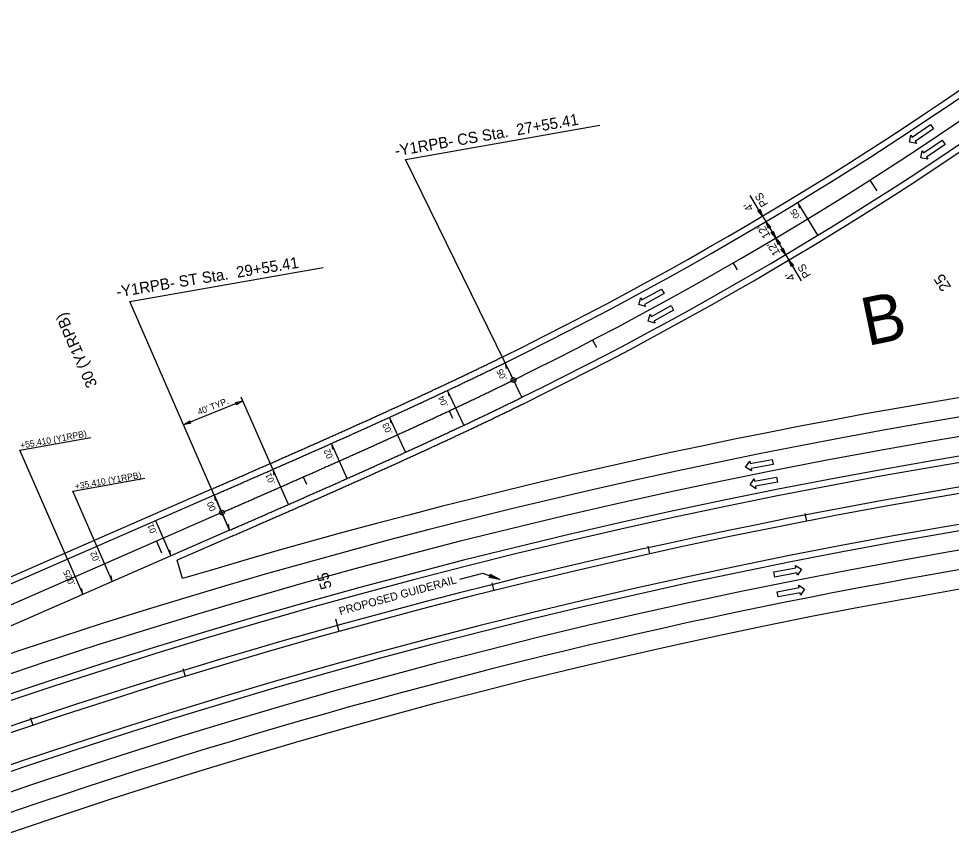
# Model space of a CAD drawing. Extents: x 2389099 to 2405615, y 552200 to 573532.
# Drawn here: x 2393606 to 2394188, y 553993 to 554498 of the extents above; entities that cross this region are included whole.
import ezdxf

# ---------------------------------------------------------------- set-up
doc = ezdxf.new("R2010")
doc.units = 0
for name, color, linetype in [('Old_Level_11', 7, 'Continuous'), ('Prop Cable Guiderail Double Face', 7, 'Continuous'), ('Prop Dimension', 7, 'Continuous'), ('Prop Dimension Text', 7, 'Continuous'), ('Prop DSN Text', 7, 'Continuous'), ('Prop EOT', 7, 'Continuous'), ('Prop Horizontal Alignment', 7, 'Continuous'), ('Prop Horizontal Alignment Curve and Spiral Data', 7, 'Continuous'), ('Prop Horizontal Alignment Tick Large', 7, 'Continuous'), ('Prop Horizontal Alignment Tick Small', 7, 'Continuous'), ('Prop Lane Arrow Through CELL', 7, 'Continuous'), ('Prop Lane Lines', 7, 'Continuous'), ('Prop Super Arrow 1 Lane CELL', 7, 'Continuous'), ('Prop Superelevation Label', 7, 'Continuous')]:
    doc.layers.add(name, color=color, linetype=linetype)

# ---------------------------------------------------------------- blocks, each defined once
blk = doc.blocks.new('TERM')
at = {"layer": 'Old_Level_11'}
blk.add_lwpolyline([(-0.01375, 0.00225), (0, 0), (-0.01375, -0.0025), (-0.012, 0)], close=True, dxfattribs=at)

msp = doc.modelspace()

# ---------------------------------------------------------------- linework, layer by layer
at = {"layer": 'Prop Cable Guiderail Double Face'}
msp.add_arc((2394828.31, 550434.92), 3824, 87.04844, 123.9393, dxfattribs=at)
at = {"layer": 'Prop Dimension'}
for p, q in [((2394070.15, 554374.95), (2394062.49, 554387.84)), ((2394070.15, 554374.95), (2394072.2, 554371.51)), ((2394072.2, 554371.51), (2394078.33, 554361.2)), ((2394078.33, 554361.2), (2394084.47, 554350.88)), ((2394084.47, 554350.88), (2394086.51, 554347.45)), ((2394086.51, 554347.45), (2394094.18, 554334.55)), ((2393745.54, 554259.59), (2393708.53, 554244.62)), ((2393764.32, 554216.83), (2393744.51, 554261.92)), ((2393606.31, 554228.81), (2393650.67, 554236.64)), ((2393636.07, 554160.75), (2393606.31, 554228.81)), ((2393639.3, 554203.29), (2393684.31, 554211.22)), ((2393654.39, 554168.76), (2393639.3, 554203.29))]:
    msp.add_line(p, q, dxfattribs=at)
for points in [[(2394068.52, 554379.21), (2394070.15, 554374.95), (2394067.15, 554378.43), (2394068.13, 554378.34)], [(2394073.83, 554367.25), (2394072.2, 554371.51), (2394075.2, 554368.03), (2394074.22, 554368.12)], [(2394076.7, 554365.46), (2394078.33, 554361.2), (2394075.33, 554364.68), (2394076.31, 554364.59)], [(2394079.97, 554356.93), (2394078.33, 554361.2), (2394081.33, 554357.72), (2394080.35, 554357.8)], [(2394082.83, 554355.15), (2394084.47, 554350.88), (2394081.47, 554354.36), (2394082.45, 554354.28)], [(2394088.15, 554343.18), (2394086.51, 554347.45), (2394089.51, 554343.97), (2394088.53, 554344.05)], [(2393741.07, 554258.62), (2393745.54, 554259.59), (2393741.64, 554257.15), (2393741.87, 554258.11)], [(2393712.99, 554245.59), (2393708.53, 554244.62), (2393712.43, 554247.06), (2393712.19, 554246.11)]]:
    msp.add_lwpolyline(points, close=True, dxfattribs=at)
at = {"layer": 'Prop DSN Text'}
for p, q in [((2393881.08, 554148.27), (2393895.46, 554151.99)), ((2393895.46, 554151.99), (2393906.12, 554148.02))]:
    msp.add_line(p, q, dxfattribs=at)
at = {"layer": 'Prop EOT'}
for p, q in [((2393726.04, 554204.45), (2393359.53, 554044.22)), ((2393727.64, 554200.78), (2393361.13, 554040.55)), ((2393737.25, 554178.79), (2393527.93, 554087.28)), ((2393738.86, 554175.13), (2393704.44, 554160.08)), ((2393707.9, 554148.58), (2393704.44, 554160.08))]:
    msp.add_line(p, q, dxfattribs=at)
for centre, radius, start, end in [((2392902.55, 556337.94), 2284, 296.10428, 342.30241), ((2392902.55, 556337.94), 2288, 296.10428, 342.30241), ((2392902.55, 556337.94), 2312, 296.10428, 342.30241), ((2392902.55, 556337.94), 2316, 296.10428, 342.30241), ((2394828.31, 550434.92), 3879, 67.475, 106.78848), ((2394828.31, 550434.92), 3867, 59.69891, 109.59769), ((2394828.31, 550434.92), 3843, 59.69891, 123.9393), ((2394828.31, 550434.92), 3839, 59.69891, 123.9393), ((2394828.31, 550434.92), 3801, 59.69891, 123.9393), ((2394828.31, 550434.92), 3797, 59.69891, 123.9393), ((2394828.31, 550434.92), 3773, 89.80344, 120.03622), ((2394828.31, 550434.92), 3761, 90.54697, 120.03622)]:
    msp.add_arc(centre, radius, start, end, dxfattribs=at)
for points in [[(2393726.09, 554204.46), (2393728.57, 554205.55), (2393731.05, 554206.63), (2393733.52, 554207.71), (2393736, 554208.79), (2393738.47, 554209.88), (2393740.95, 554210.96), (2393743.42, 554212.04), (2393745.9, 554213.12), (2393748.37, 554214.21), (2393750.84, 554215.29), (2393753.32, 554216.37), (2393755.79, 554217.46), (2393758.26, 554218.54), (2393760.73, 554219.63), (2393763.2, 554220.71), (2393765.67, 554221.8), (2393768.14, 554222.88), (2393770.61, 554223.97), (2393773.08, 554225.06), (2393775.55, 554226.15), (2393778.02, 554227.24), (2393780.49, 554228.33), (2393782.95, 554229.42), (2393785.42, 554230.51), (2393787.89, 554231.6), (2393790.35, 554232.69), (2393792.81, 554233.78), (2393795.28, 554234.88), (2393797.74, 554235.98), (2393800.2, 554237.07), (2393802.66, 554238.17), (2393805.13, 554239.27), (2393807.58, 554240.37), (2393810.04, 554241.47), (2393812.5, 554242.57), (2393814.96, 554243.68), (2393817.42, 554244.78), (2393819.87, 554245.89), (2393822.33, 554246.99), (2393824.78, 554248.1), (2393827.23, 554249.21), (2393829.68, 554250.33), (2393832.13, 554251.44), (2393834.58, 554252.55), (2393837.03, 554253.67), (2393839.48, 554254.79), (2393841.93, 554255.91), (2393844.37, 554257.03), (2393846.82, 554258.15), (2393849.26, 554259.28), (2393851.7, 554260.41), (2393854.14, 554261.54), (2393856.58, 554262.67), (2393859.02, 554263.8), (2393861.46, 554264.93), (2393863.9, 554266.07), (2393866.33, 554267.21), (2393868.77, 554268.35), (2393871.2, 554269.49), (2393873.63, 554270.64), (2393876.06, 554271.79), (2393878.49, 554272.94), (2393880.92, 554274.09), (2393883.34, 554275.24), (2393885.77, 554276.4), (2393888.19, 554277.56), (2393890.61, 554278.72), (2393893.03, 554279.89), (2393895.45, 554281.05), (2393897.87, 554282.22), (2393900.28, 554283.39), (2393902.7, 554284.57), (2393905.11, 554285.74), (2393907.53, 554286.93)], [(2393727.7, 554200.8), (2393730.17, 554201.88), (2393732.65, 554202.96), (2393735.12, 554204.05), (2393737.6, 554205.13), (2393740.08, 554206.21), (2393742.55, 554207.29), (2393745.03, 554208.38), (2393747.5, 554209.46), (2393749.97, 554210.54), (2393752.45, 554211.63), (2393754.92, 554212.71), (2393757.4, 554213.8), (2393759.87, 554214.88), (2393762.34, 554215.96), (2393764.81, 554217.05), (2393767.28, 554218.14), (2393769.75, 554219.22), (2393772.23, 554220.31), (2393774.7, 554221.4), (2393777.17, 554222.49), (2393779.64, 554223.58), (2393782.1, 554224.67), (2393784.57, 554225.76), (2393787.04, 554226.85), (2393789.51, 554227.94), (2393791.97, 554229.03), (2393794.44, 554230.13), (2393796.9, 554231.22), (2393799.37, 554232.32), (2393801.83, 554233.42), (2393804.29, 554234.52), (2393806.76, 554235.62), (2393809.22, 554236.72), (2393811.68, 554237.82), (2393814.14, 554238.92), (2393816.6, 554240.03), (2393819.06, 554241.13), (2393821.52, 554242.24), (2393823.97, 554243.35), (2393826.43, 554244.46), (2393828.88, 554245.57), (2393831.34, 554246.68), (2393833.79, 554247.8), (2393836.24, 554248.91), (2393838.69, 554250.03), (2393841.14, 554251.15), (2393843.59, 554252.27), (2393846.04, 554253.4), (2393848.49, 554254.52), (2393850.94, 554255.65), (2393853.38, 554256.78), (2393855.83, 554257.91), (2393858.27, 554259.04), (2393860.71, 554260.17), (2393863.15, 554261.31), (2393865.59, 554262.45), (2393868.03, 554263.59), (2393870.47, 554264.73), (2393872.9, 554265.88), (2393875.34, 554267.02), (2393877.77, 554268.17), (2393880.2, 554269.32), (2393882.63, 554270.48), (2393885.06, 554271.63), (2393887.49, 554272.79), (2393889.92, 554273.95), (2393892.34, 554275.12), (2393894.77, 554276.28), (2393897.19, 554277.45), (2393899.61, 554278.62), (2393902.03, 554279.79), (2393904.45, 554280.97), (2393906.87, 554282.15), (2393909.29, 554283.33)], [(2393737.31, 554178.81), (2393739.79, 554179.89), (2393742.26, 554180.97), (2393744.74, 554182.06), (2393747.22, 554183.14), (2393749.69, 554184.22), (2393752.17, 554185.31), (2393754.65, 554186.39), (2393757.12, 554187.47), (2393759.6, 554188.56), (2393762.08, 554189.64), (2393764.56, 554190.73), (2393767.03, 554191.82), (2393769.51, 554192.9), (2393771.99, 554193.99), (2393774.46, 554195.08), (2393776.94, 554196.17), (2393779.42, 554197.26), (2393781.9, 554198.35), (2393784.37, 554199.44), (2393786.85, 554200.53), (2393789.33, 554201.62), (2393791.8, 554202.71), (2393794.28, 554203.81), (2393796.75, 554204.9), (2393799.23, 554206), (2393801.7, 554207.1), (2393804.18, 554208.2), (2393806.65, 554209.29), (2393809.13, 554210.4), (2393811.6, 554211.5), (2393814.08, 554212.6), (2393816.55, 554213.7), (2393819.02, 554214.81), (2393821.49, 554215.92), (2393823.97, 554217.03), (2393826.44, 554218.14), (2393828.91, 554219.25), (2393831.38, 554220.36), (2393833.85, 554221.48), (2393836.32, 554222.59), (2393838.79, 554223.71), (2393841.26, 554224.83), (2393843.73, 554225.95), (2393846.19, 554227.07), (2393848.66, 554228.2), (2393851.13, 554229.33), (2393853.59, 554230.45), (2393856.06, 554231.59), (2393858.52, 554232.72), (2393860.98, 554233.85), (2393863.45, 554234.99), (2393865.91, 554236.13), (2393868.37, 554237.27), (2393870.83, 554238.41), (2393873.29, 554239.56), (2393875.75, 554240.7), (2393878.21, 554241.85), (2393880.66, 554243), (2393883.12, 554244.16), (2393885.58, 554245.32), (2393888.03, 554246.47), (2393890.48, 554247.64), (2393892.93, 554248.8), (2393895.39, 554249.97), (2393897.84, 554251.14), (2393900.29, 554252.31), (2393902.73, 554253.48), (2393905.18, 554254.66), (2393907.63, 554255.84), (2393910.07, 554257.02), (2393912.52, 554258.21), (2393914.96, 554259.39), (2393917.4, 554260.59), (2393919.83, 554261.78)], [(2393738.91, 554175.14), (2393741.39, 554176.23), (2393743.87, 554177.31), (2393746.34, 554178.39), (2393748.82, 554179.47), (2393751.3, 554180.56), (2393753.77, 554181.64), (2393756.25, 554182.73), (2393758.73, 554183.81), (2393761.21, 554184.9), (2393763.68, 554185.98), (2393766.16, 554187.07), (2393768.64, 554188.15), (2393771.12, 554189.24), (2393773.6, 554190.33), (2393776.07, 554191.42), (2393778.55, 554192.5), (2393781.03, 554193.59), (2393783.51, 554194.68), (2393785.99, 554195.78), (2393788.46, 554196.87), (2393790.94, 554197.96), (2393793.42, 554199.05), (2393795.9, 554200.15), (2393798.37, 554201.24), (2393800.85, 554202.34), (2393803.33, 554203.44), (2393805.8, 554204.54), (2393808.28, 554205.64), (2393810.75, 554206.74), (2393813.23, 554207.84), (2393815.71, 554208.95), (2393818.18, 554210.05), (2393820.66, 554211.16), (2393823.13, 554212.27), (2393825.6, 554213.38), (2393828.08, 554214.49), (2393830.55, 554215.6), (2393833.02, 554216.71), (2393835.5, 554217.83), (2393837.97, 554218.95), (2393840.44, 554220.07), (2393842.91, 554221.19), (2393845.38, 554222.31), (2393847.85, 554223.43), (2393850.32, 554224.56), (2393852.79, 554225.69), (2393855.26, 554226.82), (2393857.73, 554227.95), (2393860.19, 554229.08), (2393862.66, 554230.22), (2393865.12, 554231.36), (2393867.59, 554232.5), (2393870.05, 554233.64), (2393872.52, 554234.78), (2393874.98, 554235.93), (2393877.44, 554237.08), (2393879.9, 554238.23), (2393882.36, 554239.38), (2393884.82, 554240.54), (2393887.28, 554241.7), (2393889.74, 554242.86), (2393892.2, 554244.02), (2393894.65, 554245.19), (2393897.11, 554246.36), (2393899.56, 554247.53), (2393902.01, 554248.7), (2393904.47, 554249.88), (2393906.92, 554251.05), (2393909.37, 554252.24), (2393911.82, 554253.42), (2393914.26, 554254.61), (2393916.71, 554255.8), (2393919.16, 554256.99), (2393921.59, 554258.18)]]:
    msp.add_spline(points, degree=3, dxfattribs=at)
at = {"layer": 'Prop Horizontal Alignment'}
msp.add_line((2393732.5, 554189.8), (2393365.99, 554029.58), dxfattribs=at)
for centre, radius, start, end in [((2392902.55, 556337.94), 2300, 296.10428, 342.30241), ((2394828.31, 550434.92), 3820, 59.69891, 123.9393)]:
    msp.add_arc(centre, radius, start, end, dxfattribs=at)
msp.add_spline([(2393732.5, 554189.8), (2393734.98, 554190.89), (2393737.46, 554191.97), (2393739.93, 554193.05), (2393742.41, 554194.13), (2393744.88, 554195.22), (2393747.36, 554196.3), (2393749.84, 554197.38), (2393752.31, 554198.47), (2393754.79, 554199.55), (2393757.26, 554200.64), (2393759.74, 554201.72), (2393762.21, 554202.81), (2393764.69, 554203.89), (2393767.16, 554204.98), (2393769.64, 554206.06), (2393772.11, 554207.15), (2393774.59, 554208.24), (2393777.06, 554209.33), (2393779.53, 554210.42), (2393782.01, 554211.51), (2393784.48, 554212.6), (2393786.95, 554213.69), (2393789.42, 554214.78), (2393791.9, 554215.88), (2393794.37, 554216.97), (2393796.84, 554218.07), (2393799.31, 554219.16), (2393801.78, 554220.26), (2393804.25, 554221.36), (2393806.72, 554222.46), (2393809.19, 554223.56), (2393811.65, 554224.66), (2393814.12, 554225.76), (2393816.59, 554226.87), (2393819.05, 554227.97), (2393821.52, 554229.08), (2393823.98, 554230.19), (2393826.45, 554231.3), (2393828.91, 554232.41), (2393831.37, 554233.53), (2393833.84, 554234.64), (2393836.3, 554235.76), (2393838.76, 554236.87), (2393841.22, 554237.99), (2393843.68, 554239.12), (2393846.14, 554240.24), (2393848.59, 554241.36), (2393851.05, 554242.49), (2393853.5, 554243.62), (2393855.96, 554244.75), (2393858.41, 554245.88), (2393860.87, 554247.02), (2393863.32, 554248.15), (2393865.77, 554249.29), (2393868.22, 554250.43), (2393870.67, 554251.58), (2393873.12, 554252.72), (2393875.56, 554253.87), (2393878.01, 554255.02), (2393880.46, 554256.17), (2393882.9, 554257.32), (2393885.34, 554258.48), (2393887.78, 554259.64), (2393890.22, 554260.8), (2393892.66, 554261.96), (2393895.1, 554263.13), (2393897.54, 554264.3), (2393899.97, 554265.47), (2393902.41, 554266.64), (2393904.84, 554267.82), (2393907.27, 554269), (2393909.7, 554270.18), (2393912.13, 554271.37), (2393914.56, 554272.56)], degree=3, dxfattribs=at)
at = {"layer": 'Prop Horizontal Alignment Curve and Spiral Data'}
for p, q in [((2393847.07, 554410.29), (2393968.58, 554431.72)), ((2393913.9, 554273.9), (2393847.07, 554410.29)), ((2393674.91, 554321.55), (2393795.81, 554342.87)), ((2393731.9, 554191.18), (2393674.91, 554321.55))]:
    msp.add_line(p, q, dxfattribs=at)
for centre in [(2393914.56, 554272.56), (2393732.5, 554189.8)]:
    msp.add_circle(centre, 1.5, dxfattribs=at)
at = {"layer": 'Prop Horizontal Alignment Tick Large'}
for p, q in [((2394137.21, 554397.43), (2394141.51, 554390.68)), ((2393691.65, 554171.94), (2393694.85, 554164.61)), ((2393805.78, 554115.52), (2393803.64, 554123.23))]:
    msp.add_line(p, q, dxfattribs=at)
at = {"layer": 'Prop Horizontal Alignment Tick Small'}
for p, q in [((2394051.7, 554345.6), (2394054.2, 554341.27)), ((2393964.02, 554297.53), (2393966.33, 554293.1)), ((2393874.35, 554253.3), (2393876.47, 554248.77)), ((2393783.25, 554212.05), (2393785.27, 554207.48)), ((2394097.69, 554184.39), (2394096.73, 554189.3)), ((2393999.79, 554163.99), (2393998.71, 554168.87)), ((2393902.47, 554141.02), (2393901.26, 554145.87)), ((2393709.79, 554087.49), (2393708.33, 554092.27)), ((2393614.57, 554056.96), (2393612.98, 554061.7))]:
    msp.add_line(p, q, dxfattribs=at)
at = {"layer": 'Prop Lane Arrow Through CELL'}
for p, q in [((2394163.49, 554424.2), (2394175.04, 554432.1)), ((2394175.04, 554432.1), (2394176.9, 554429.38)), ((2394176.9, 554429.38), (2394165.35, 554421.48)), ((2394161.85, 554421.02), (2394162.64, 554425.44)), ((2394166.19, 554420.24), (2394161.85, 554421.02)), ((2394162.64, 554425.44), (2394163.49, 554424.2)), ((2394165.35, 554421.48), (2394166.19, 554420.24)), ((2394170.67, 554414.37), (2394182.23, 554422.28)), ((2394182.23, 554422.28), (2394184.09, 554419.55)), ((2394169.03, 554411.19), (2394169.83, 554415.61)), ((2394169.83, 554415.61), (2394170.67, 554414.37)), ((2394184.09, 554419.55), (2394172.54, 554411.65)), ((2394173.38, 554410.41), (2394169.03, 554411.19)), ((2394172.54, 554411.65), (2394173.38, 554410.41)), ((2393994.82, 554322.67), (2394007.11, 554329.38)), ((2394007.11, 554329.38), (2394008.69, 554326.49)), ((2393992.87, 554319.67), (2393994.1, 554323.99)), ((2393994.1, 554323.99), (2393994.82, 554322.67)), ((2394008.69, 554326.49), (2393996.4, 554319.78)), ((2393997.12, 554318.46), (2393992.87, 554319.67)), ((2393996.4, 554319.78), (2393997.12, 554318.46)), ((2394000.73, 554312.28), (2394013.02, 554319)), ((2394014.6, 554316.1), (2394002.31, 554309.39)), ((2394013.02, 554319), (2394014.6, 554316.1)), ((2393998.78, 554309.28), (2394000.01, 554313.6)), ((2394000.01, 554313.6), (2394000.73, 554312.28)), ((2394003.03, 554308.07), (2393998.78, 554309.28)), ((2394002.31, 554309.39), (2394003.03, 554308.07)), ((2394062.36, 554220.51), (2394076.13, 554223.05)), ((2394076.13, 554223.05), (2394076.73, 554219.81)), ((2394059.57, 554218.26), (2394062.09, 554221.98)), ((2394063.23, 554215.79), (2394059.57, 554218.26)), ((2394062.09, 554221.98), (2394062.36, 554220.51)), ((2394076.73, 554219.81), (2394062.96, 554217.26)), ((2394062.96, 554217.26), (2394063.23, 554215.79)), ((2394062.36, 554207.22), (2394064.87, 554210.94)), ((2394064.87, 554210.94), (2394065.15, 554209.46)), ((2394065.15, 554209.46), (2394078.91, 554212.01)), ((2394078.91, 554212.01), (2394079.51, 554208.76)), ((2394066.02, 554204.74), (2394062.36, 554207.22)), ((2394079.51, 554208.76), (2394065.75, 554206.22)), ((2394065.75, 554206.22), (2394066.02, 554204.74)), ((2394077.24, 554152.84), (2394091.01, 554155.41)), ((2394077.85, 554149.59), (2394077.24, 554152.84)), ((2394091.01, 554155.41), (2394090.73, 554156.88)), ((2394090.73, 554156.88), (2394094.4, 554154.41)), ((2394094.4, 554154.41), (2394091.89, 554150.69)), ((2394091.61, 554152.16), (2394077.85, 554149.59)), ((2394091.89, 554150.69), (2394091.61, 554152.16)), ((2394079.24, 554140.43), (2394093, 554142.99)), ((2394093, 554142.99), (2394092.73, 554144.47)), ((2394092.73, 554144.47), (2394096.39, 554142)), ((2394096.39, 554142), (2394093.88, 554138.28)), ((2394079.85, 554137.18), (2394079.24, 554140.43)), ((2394093.61, 554139.75), (2394079.85, 554137.18)), ((2394093.88, 554138.28), (2394093.61, 554139.75))]:
    msp.add_line(p, q, dxfattribs=at)
at = {"layer": 'Prop Lane Lines'}
for radius in [3855, 3785]:
    msp.add_arc((2394828.31, 550434.92), radius, 59.69891, 123.9393, dxfattribs=at)
at = {"layer": 'Prop Super Arrow 1 Lane CELL'}
for p, q in [((2394104.58, 554362.99), (2394092.1, 554383.49)), ((2393919.84, 554261.78), (2393909.28, 554283.33)), ((2393883.61, 554244.39), (2393873.39, 554266.1)), ((2393847.18, 554227.52), (2393837.22, 554249.36)), ((2393810.61, 554211.06), (2393800.85, 554232.98)), ((2393773.97, 554194.86), (2393764.32, 554216.83)), ((2393737.31, 554178.81), (2393727.7, 554200.8)), ((2393727.7, 554200.8), (2393737.31, 554178.81)), ((2393691.04, 554184.78), (2393700.66, 554162.79)), ((2393654.39, 554168.75), (2393664.01, 554146.76)), ((2393636.07, 554160.74), (2393645.68, 554138.75))]:
    msp.add_line(p, q, dxfattribs=at)
for points in [[(2394092.1, 554383.49), (2394093.24, 554380.08), (2394093.64, 554380.97)], [(2393909.28, 554283.33), (2393910.1, 554279.84), (2393910.58, 554280.68)], [(2393873.39, 554266.1), (2393874.16, 554262.6), (2393874.65, 554263.44)], [(2393837.22, 554249.36), (2393837.95, 554245.84), (2393838.45, 554246.68)], [(2393800.85, 554232.98), (2393801.54, 554229.46), (2393802.05, 554230.28)], [(2393764.32, 554216.83), (2393764.99, 554213.31), (2393765.5, 554214.13)], [(2393727.7, 554200.8), (2393728.36, 554197.27), (2393728.88, 554198.09)], [(2393737.31, 554178.81), (2393736.64, 554182.33), (2393736.13, 554181.51)], [(2393700.66, 554162.79), (2393699.99, 554166.31), (2393699.48, 554165.49)], [(2393664.01, 554146.76), (2393663.34, 554150.29), (2393662.83, 554149.47)], [(2393645.68, 554138.75), (2393645.01, 554142.28), (2393644.5, 554141.45)]]:
    msp.add_lwpolyline(points, close=True, dxfattribs=at)

# ---------------------------------------------------------------- block references
at = {"layer": 'Prop DSN Text', "xscale": 499.99999999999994, "yscale": 499.9999999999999, "rotation": -20.424489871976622}
msp.add_blockref('TERM', (2393906.12, 554148.02), dxfattribs=at)

# ---------------------------------------------------------------- texts
at = {"layer": 'Prop Dimension Text'}
for s, height, rotation, p in [('PS', 5, 120.74504, (2394073.84, 554382.44)), ("4'", 5, 120.74504, (2394064.76, 554379.73)), ("12'", 5, 120.74447, (2394075.25, 554362.71)), ("12'", 5, 120.74418, (2394081.34, 554351.9)), ('PS', 5, 120.74449, (2394100.53, 554338)), ("4'", 5, 120.74449, (2394090.77, 554336.21)), ("40' TYP.", 4, 21.21959, (2393718.17, 554250.6)), ('+55.410 (Y1RPB)', 4, 10.35359, (2393606.92, 554229.67)), ('+35.410 (Y1RPB)', 4, 9.99981, (2393641.03, 554204.16))]:
    msp.add_text(s, height=height, rotation=rotation, dxfattribs=at).set_placement(p)
at = {"layer": 'Prop DSN Text'}
msp.add_text('PROPOSED GUIDERAIL', height=5, rotation=15.34335, dxfattribs=at).set_placement((2393806.36, 554125.72))
at = {"layer": 'Prop Horizontal Alignment Curve and Spiral Data'}
for s, height, rotation, p in [('-Y1RPB- CS Sta.  27+55.41', 7, 9.84917, (2393841.09, 554412.12)), ('-Y1RPB- ST Sta.  29+55.41', 7, 9.27488, (2393667.11, 554324.11)), ('25', 7, 122.46684, (2394188.12, 554330.78)), ('B', 30, 11.59021, (2394135.41, 554293.69)), ('30 (Y1RPB)', 7, 113.61316, (2393654.81, 554269.58)), ('55', 7, 105.52616, (2393801.2, 554143.01))]:
    msp.add_text(s, height=height, rotation=rotation, dxfattribs=at).set_placement(p)
at = {"layer": 'Prop Superelevation Label'}
for s, rotation, p in [('.05', 121.32683, (2394094.39, 554373.62)), ('.05', 116.10427, (2393910.66, 554273.3)), ('.04', 115.20746, (2393873.98, 554256.55)), ('.03', 114.50995, (2393839.19, 554239.62)), ('.02', 114.01173, (2393802.58, 554223.26)), ('.01', 113.7128, (2393765.91, 554208.2)), ('00', 293.61316, (2393722.88, 554195.63)), ('.01', 113.61316, (2393692.25, 554176.63)), ('.02', 113.61316, (2393656.62, 554159.37)), ('.025', 113.61316, (2393641.01, 554144.95))]:
    msp.add_text(s, height=4, rotation=rotation, dxfattribs=at).set_placement(p)

doc.saveas('drawing.dxf')
